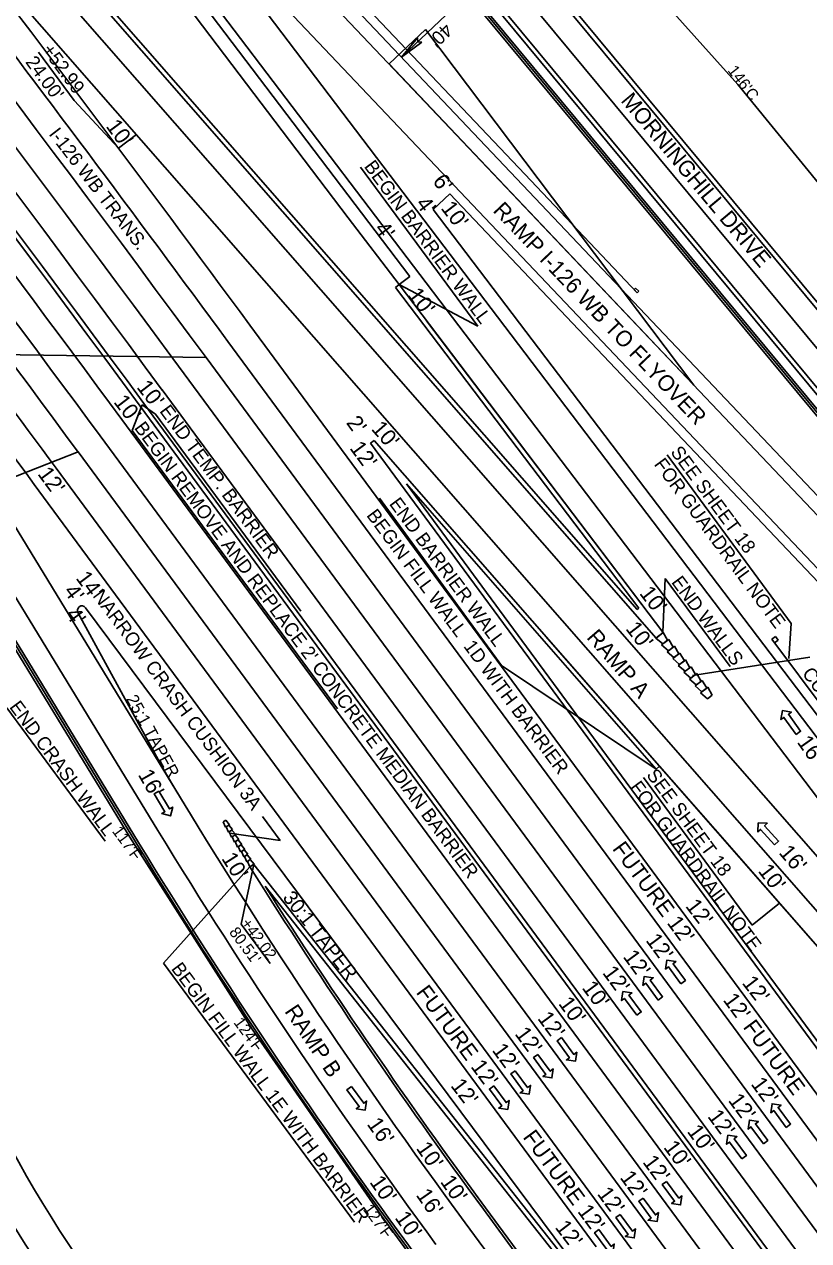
# Model space of a CAD drawing. Extents: x 1966090 to 1975830, y 788086 to 801233.
# Drawn here: x 1970435 to 1970780, y 796566 to 797102 of the extents above; entities that cross this region are included whole.
import ezdxf

# ---------------------------------------------------------------- set-up
doc = ezdxf.new("R2010")
doc.units = 0
for name, color, linetype in [('BR_PRESTRESSED BEAM', 7, 'Continuous'), ('BR_PROPOSED_DRAINAGE', 7, 'Continuous'), ('BR_REBAR', 7, 'Continuous'), ('RD_EX_Driveway_txCode', 7, 'Continuous'), ('RD_EX_RW_TX', 7, 'Continuous'), ('RD_EX_SU_Gas', 7, 'Continuous'), ('RD_EX_SU_H2O', 7, 'Continuous'), ('RD_EX_Survey_Limits', 7, 'Continuous'), ('RD_EX_TX_BldgApp_ELEV', 7, 'Continuous'), ('RD_EX_TX_Dam_ELEV', 7, 'Continuous'), ('RD_PD_Final_LnLine', 7, 'Continuous'), ('RD_PD_PaveShd', 7, 'Continuous'), ('RD_Sketch6', 7, 'Continuous'), ('RD_Sketch8', 7, 'Continuous'), ('RD_Sketch9', 7, 'Continuous')]:
    doc.layers.add(name, color=color, linetype=linetype)

msp = doc.modelspace()

# ---------------------------------------------------------------- linework, layer by layer
at = {"layer": 'BR_PRESTRESSED BEAM'}
for p, q in [((1970340.58, 797367.47), (1970655.12, 797035.82)), ((1970458.41, 797173.24), (1970577.36, 797016.6)), ((1970655.12, 797035.82), (1970704.66, 796983.58)), ((1970599.73, 796987.13), (1970577.36, 797016.6)), ((1970703.83, 796985.55), (1970703.29, 796985.03)), ((1970703.29, 796985.03), (1970704.66, 796983.58)), ((1970705.39, 796984.27), (1970703.83, 796985.55)), ((1970704.66, 796983.58), (1970705.39, 796984.27)), ((1970763.84, 796831), (1970765.45, 796832.2)), ((1970765.45, 796832.2), (1970766.64, 796830.6)), ((1970787.81, 796798.98), (1970763.84, 796831)), ((1970765.04, 796829.4), (1970763.84, 796831)), ((1970766.64, 796830.6), (1970765.04, 796829.4)), ((1970738.79, 796747.3), (1970714.42, 796775.13)), ((1970738.79, 796747.3), (1971033.24, 796411.1))]:
    msp.add_line(p, q, dxfattribs=at)
at = {"layer": 'BR_PROPOSED_DRAINAGE'}
for p, q in [((1970682.04, 797150.08), (1970748.85, 797075.26)), ((1970748.85, 797075.26), (1970875.59, 796920.37)), ((1970428.93, 796829.58), (1970481.23, 796743.9)), ((1970481.23, 796743.9), (1970535, 796659.31)), ((1970535, 796659.31), (1970591.97, 796577.07)), ((1970591.97, 796577.07), (1970651.22, 796496.51))]:
    msp.add_line(p, q, dxfattribs=at)
at = {"layer": 'BR_REBAR'}
for p, q in [((1970208.64, 797407.27), (1970712.9, 796831.5)), ((1970210.14, 797408.59), (1970704.59, 796844.03)), ((1970626.99, 797118.22), (1970963.53, 796712.5)), ((1970628.53, 797119.5), (1970965.07, 796713.78)), ((1970599.73, 796987.13), (1970598.14, 796985.92)), ((1970598.14, 796985.92), (1970705.39, 796844.7)), ((1970611.83, 796971.2), (1970715.91, 796834.14)), ((1970377.42, 796917.81), (1970485.02, 796741.53)), ((1970587.2, 796917.36), (1970588.81, 796918.54)), ((1970588.81, 796918.54), (1970714.42, 796775.13)), ((1970376.57, 796917.29), (1970484.16, 796741.01)), ((1970587.2, 796917.36), (1970691.5, 796775.88)), ((1970602.95, 796899.36), (1970693.11, 796777.07)), ((1970602.95, 796899.36), (1970712.91, 796773.81)), ((1970704.59, 796844.03), (1970705.39, 796844.7)), ((1970716, 796834.02), (1970712.94, 796831.45)), ((1970691.5, 796775.88), (1971027.63, 796319.93)), ((1970693.11, 796777.07), (1971029.24, 796321.12)), ((1970714.42, 796775.13), (1970712.91, 796773.81)), ((1970534.02, 796730.8), (1970535.71, 796731.87)), ((1970540.77, 796722.24), (1970711.09, 796506.63)), ((1970637.8, 796580.65), (1970763.63, 796409.96)), ((1970636.89, 796579.98), (1970762.72, 796409.3))]:
    msp.add_line(p, q, dxfattribs=at)
for radius, start in [(2527, 211.39766), (2526, 211.39766), (2490, 212.19585), (2488.88, 212.44528)]:
    msp.add_arc((1972641.14, 798057.51), radius, start, 216.39766, dxfattribs=at)
at = {"layer": 'RD_EX_Driveway_txCode'}
for points in [[(1970774.57, 796789.11), (1970776.52, 796790.5), (1970771.21, 796797.98), (1970772.53, 796798.92), (1970768.59, 796799.59), (1970767.92, 796795.64), (1970769.25, 796796.59)], [(1970493.96, 796764.12), (1970491.9, 796762.88), (1970496.64, 796755.03), (1970495.25, 796754.19), (1970499.13, 796753.23), (1970500.09, 796757.11), (1970498.7, 796756.27)], [(1970765.11, 796740.47), (1970766.88, 796742.09), (1970760.71, 796748.87), (1970761.91, 796749.97), (1970757.92, 796750.15), (1970757.73, 796746.16), (1970758.93, 796747.25)], [(1970723.89, 796679.33), (1970725.82, 796680.75), (1970720.38, 796688.13), (1970721.69, 796689.1), (1970717.73, 796689.7), (1970717.14, 796685.74), (1970718.45, 796686.71)], [(1970713.87, 796672.14), (1970715.8, 796673.56), (1970710.36, 796680.94), (1970711.67, 796681.91), (1970707.71, 796682.51), (1970707.11, 796678.55), (1970708.42, 796679.52)], [(1970704.45, 796665.47), (1970706.38, 796666.89), (1970700.94, 796674.27), (1970702.25, 796675.24), (1970698.3, 796675.84), (1970697.7, 796671.88), (1970699.01, 796672.85)], [(1970671.24, 796655.56), (1970669.31, 796654.14), (1970674.75, 796646.75), (1970673.44, 796645.79), (1970677.4, 796645.19), (1970677.99, 796649.15), (1970676.68, 796648.18)], [(1970660.9, 796648.18), (1970658.97, 796646.76), (1970664.41, 796639.38), (1970663.1, 796638.41), (1970667.05, 796637.81), (1970667.65, 796641.77), (1970666.34, 796640.8)], [(1970650.88, 796640.99), (1970648.94, 796639.57), (1970654.39, 796632.18), (1970653.07, 796631.22), (1970657.03, 796630.62), (1970657.63, 796634.57), (1970656.32, 796633.61)], [(1970578.74, 796634.06), (1970576.8, 796632.64), (1970582.22, 796625.24), (1970580.91, 796624.28), (1970584.86, 796623.67), (1970585.47, 796627.62), (1970584.16, 796626.66)], [(1970641.46, 796634.32), (1970639.53, 796632.9), (1970644.97, 796625.51), (1970643.66, 796624.55), (1970647.62, 796623.95), (1970648.21, 796627.91), (1970646.9, 796626.94)], [(1970770.19, 796616.07), (1970772.12, 796617.49), (1970766.67, 796624.87), (1970767.99, 796625.84), (1970764.03, 796626.44), (1970763.43, 796622.48), (1970764.74, 796623.45)], [(1970760.16, 796608.88), (1970762.1, 796610.3), (1970756.65, 796617.68), (1970757.96, 796618.65), (1970754.01, 796619.25), (1970753.41, 796615.29), (1970754.72, 796616.26)], [(1970750.75, 796602.21), (1970752.68, 796603.63), (1970747.24, 796611.01), (1970748.55, 796611.98), (1970744.59, 796612.58), (1970744, 796608.62), (1970745.31, 796609.59)], [(1970717.54, 796592.3), (1970715.61, 796590.88), (1970721.05, 796583.5), (1970719.74, 796582.53), (1970723.69, 796581.93), (1970724.29, 796585.89), (1970722.98, 796584.92)], [(1970707.19, 796584.92), (1970705.26, 796583.5), (1970710.7, 796576.12), (1970709.39, 796575.15), (1970713.35, 796574.55), (1970713.95, 796578.51), (1970712.64, 796577.54)], [(1970697.17, 796577.73), (1970695.24, 796576.31), (1970700.68, 796568.92), (1970699.37, 796567.96), (1970703.33, 796567.36), (1970703.92, 796571.32), (1970702.61, 796570.35)], [(1970687.76, 796571.06), (1970685.83, 796569.64), (1970691.27, 796562.26), (1970689.96, 796561.29), (1970693.91, 796560.69), (1970694.51, 796564.65), (1970693.2, 796563.68)]]:
    msp.add_lwpolyline(points, close=True, dxfattribs=at)
at = {"layer": 'RD_EX_SU_Gas'}
for p, q in [((1970514.75, 796954.97), (1971123.99, 796128.55)), ((1970505.09, 796947.85), (1971239.95, 795951.02)), ((1970468.06, 796920.55), (1971202.93, 795923.73)), ((1970458.41, 796913.43), (1971193.27, 795916.61))]:
    msp.add_line(p, q, dxfattribs=at)
for centre, radius, start, end in [((1958843.44, 788350.87), 14500, 36.397656, 39.566224), ((1958843.44, 788350.87), 14488, 36.397656, 39.566224), ((1961201.85, 790089.49), 11512, 36.397656, 39.351802), ((1961201.85, 790089.49), 11500, 36.397656, 39.351802), ((1970931.23, 796880.36), 600, 202.42407, 234.38356)]:
    msp.add_arc(centre, radius, start, end, dxfattribs=at)
at = {"layer": 'RD_EX_Survey_Limits'}
msp.add_line((1970371.42, 797456.09), (1970870.17, 796854.82), dxfattribs=at)
at = {"layer": 'RD_EX_TX_BldgApp_ELEV'}
for p, q in [((1970716.07, 796833.94), (1970712.87, 796831.53)), ((1970717.99, 796830.53), (1970716.07, 796833.94)), ((1970712.87, 796831.53), (1970715.86, 796828.92)), ((1970718.53, 796830.93), (1970715.33, 796828.52)), ((1970715.33, 796828.52), (1970718.32, 796825.91)), ((1970715.86, 796828.92), (1970717.99, 796830.53)), ((1970720.99, 796827.92), (1970717.79, 796825.51)), ((1970718.32, 796825.91), (1970720.45, 796827.51)), ((1970720.45, 796827.51), (1970718.53, 796830.93)), ((1970722.91, 796824.5), (1970720.99, 796827.92)), ((1970717.79, 796825.51), (1970720.78, 796822.9)), ((1970723.44, 796824.9), (1970720.25, 796822.5)), ((1970720.25, 796822.5), (1970723.24, 796819.88)), ((1970720.78, 796822.9), (1970722.91, 796824.5)), ((1970725.9, 796821.89), (1970722.71, 796819.48)), ((1970723.24, 796819.88), (1970725.37, 796821.49)), ((1970725.37, 796821.49), (1970723.44, 796824.9)), ((1970727.83, 796818.47), (1970725.9, 796821.89)), ((1970722.71, 796819.48), (1970725.7, 796816.87)), ((1970724.3, 796820.69), (1970724.3, 796820.69)), ((1970728.36, 796818.88), (1970725.17, 796816.47)), ((1970725.17, 796816.47), (1970728.16, 796813.86)), ((1970725.7, 796816.87), (1970727.83, 796818.47)), ((1970730.29, 796815.46), (1970728.36, 796818.88)), ((1970730.82, 796815.86), (1970727.62, 796813.45)), ((1970727.62, 796813.45), (1970730.62, 796810.84)), ((1970728.16, 796813.86), (1970730.29, 796815.46)), ((1970733.28, 796812.85), (1970730.08, 796810.44)), ((1970730.62, 796810.84), (1970732.75, 796812.45)), ((1970732.75, 796812.45), (1970730.82, 796815.86)), ((1970735.2, 796809.43), (1970733.28, 796812.85)), ((1970730.08, 796810.44), (1970733.07, 796807.83)), ((1970735.74, 796809.84), (1970732.54, 796807.43)), ((1970732.54, 796807.43), (1970735.53, 796804.82)), ((1970733.07, 796807.83), (1970735.2, 796809.43)), ((1970735.53, 796804.82), (1970737.66, 796806.42)), ((1970737.66, 796806.42), (1970735.74, 796809.84)), ((1970523.46, 796751.31), (1970522.22, 796750.55)), ((1970522.22, 796750.55), (1970523.25, 796748.18)), ((1970523.25, 796748.18), (1970525.12, 796749.33)), ((1970525.12, 796749.33), (1970523.46, 796751.31)), ((1970524.81, 796749.14), (1970523.57, 796748.37)), ((1970523.57, 796748.37), (1970524.6, 796746.01)), ((1970524.6, 796746.01), (1970526.46, 796747.16)), ((1970526.46, 796747.16), (1970524.81, 796749.14)), ((1970526.15, 796746.97), (1970524.91, 796746.2)), ((1970527.81, 796744.99), (1970526.15, 796746.97)), ((1970524.91, 796746.2), (1970525.95, 796743.84)), ((1970525.95, 796743.84), (1970527.81, 796744.99)), ((1970527.5, 796744.8), (1970526.26, 796744.03)), ((1970526.26, 796744.03), (1970527.29, 796741.66)), ((1970527.29, 796741.66), (1970529.15, 796742.82)), ((1970529.15, 796742.82), (1970527.5, 796744.8)), ((1970528.84, 796742.63), (1970527.6, 796741.86)), ((1970527.6, 796741.86), (1970528.64, 796739.49)), ((1970530.5, 796740.64), (1970528.84, 796742.63)), ((1970528.64, 796739.49), (1970530.5, 796740.64)), ((1970530.19, 796740.45), (1970528.95, 796739.68)), ((1970528.95, 796739.68), (1970529.98, 796737.32)), ((1970529.57, 796740.07), (1970529.57, 796740.07)), ((1970529.98, 796737.32), (1970531.85, 796738.47)), ((1970531.85, 796738.47), (1970530.19, 796740.45)), ((1970531.54, 796738.28), (1970530.29, 796737.51)), ((1970530.29, 796737.51), (1970531.33, 796735.15)), ((1970531.33, 796735.15), (1970533.19, 796736.3)), ((1970533.19, 796736.3), (1970531.54, 796738.28)), ((1970532.88, 796736.11), (1970531.64, 796735.34)), ((1970534.54, 796734.13), (1970532.88, 796736.11)), ((1970531.64, 796735.34), (1970532.68, 796732.97)), ((1970532.68, 796732.97), (1970534.54, 796734.13)), ((1970534.23, 796733.94), (1970532.99, 796733.17)), ((1970532.99, 796733.17), (1970534.02, 796730.8)), ((1970534.02, 796730.8), (1970535.88, 796731.96)), ((1970535.88, 796731.96), (1970534.23, 796733.94))]:
    msp.add_line(p, q, dxfattribs=at)
at = {"layer": 'RD_EX_TX_Dam_ELEV'}
msp.add_line((1970627.76, 797118.86), (1970899.28, 796791.53), dxfattribs=at)
at = {"layer": 'RD_PD_Final_LnLine'}
for p, q in [((1970611.34, 797099.41), (1970595.38, 797084.28)), ((1970611.34, 797099.41), (1970729.57, 796942.79)), ((1970595.38, 797084.28), (1970729.57, 796942.79))]:
    msp.add_line(p, q, dxfattribs=at)
at = {"layer": 'RD_PD_PaveShd'}
for p, q in [((1970381.42, 797464.39), (1970880.17, 796863.12)), ((1970361.41, 797447.79), (1970860.16, 796846.52)), ((1970208.64, 797407.27), (1970712.9, 796831.5)), ((1970337.68, 797364.72), (1970967.22, 796700.93)), ((1970463.19, 797176.87), (1970604.51, 796990.76)), ((1970476.15, 797047.23), (1970484.16, 797053.22)), ((1970622.06, 797027.08), (1970614.81, 797020.2)), ((1970622.06, 797027.08), (1970948.35, 796683.04)), ((1970614.81, 797020.2), (1971000.85, 796511.82)), ((1970604.51, 796990.76), (1970599.73, 796987.13)), ((1970599.73, 796987.13), (1970715.91, 796834.14)), ((1970487.38, 796934.79), (1971048.19, 796174.06)), ((1970485.77, 796933.61), (1971046.58, 796172.88)), ((1970377.42, 796917.81), (1970485.02, 796741.53)), ((1970587.2, 796917.36), (1970588.81, 796918.54)), ((1970714.42, 796775.13), (1970588.81, 796918.54)), ((1970587.2, 796917.36), (1970691.5, 796775.88)), ((1970664.28, 796832.37), (1971096.42, 796338.96)), ((1970691.5, 796775.88), (1971027.63, 796319.93)), ((1970534.02, 796730.8), (1970535.72, 796731.87)), ((1970535.72, 796731.87), (1970712.68, 796507.84)), ((1970636.89, 796579.98), (1970762.72, 796409.3))]:
    msp.add_line(p, q, dxfattribs=at)
for centre, radius, start, end in [((1972641.14, 798057.51), 2526, 211.39766, 216.39766), ((1972641.14, 798057.51), 2490, 212.19585, 216.39766), ((1970931.23, 796880.36), 572, 203.6552, 226.0941), ((1970931.23, 796880.36), 624, 203.63926, 233.79058)]:
    msp.add_arc(centre, radius, start, end, dxfattribs=at)
at = {"layer": 'RD_Sketch6'}
for p, q in [((1970600.87, 797087.33), (1970629.83, 797114.8)), ((1970607.8, 797095.84), (1970600.87, 797087.33)), ((1970607.99, 797094.09), (1970607.8, 797095.84)), ((1970600.87, 797087.33), (1970609.73, 797093.81)), ((1970609.73, 797093.81), (1970607.99, 797094.09)), ((1970582.83, 797038.79), (1970634.41, 796968.83)), ((1970634.41, 796968.83), (1970599.73, 796987.13)), ((1970296.39, 796958.41), (1970514.75, 796954.97)), ((1970482.24, 796922.91), (1970486.58, 796934.2)), ((1970492.48, 796930.11), (1970486.58, 796934.2)), ((1970556.43, 796843.37), (1970492.48, 796930.11)), ((1970482.24, 796922.91), (1970572.57, 796800.38)), ((1970334.19, 796864.86), (1970458.41, 796913.43)), ((1970717.76, 796912.12), (1970772.42, 796837.96)), ((1970591.09, 796893.11), (1970644.85, 796819.4)), ((1970716.9, 796857.74), (1970715.91, 796834.15)), ((1970716.9, 796857.74), (1970745.5, 796818.94)), ((1970772.42, 796837.96), (1970771.39, 796822.52)), ((1970780.63, 796823.08), (1970728.99, 796815.02)), ((1970644.85, 796819.4), (1970712.91, 796773.81)), ((1970470.37, 796742.03), (1970427.09, 796800.73)), ((1970707.36, 796770.04), (1970755.29, 796705.02)), ((1970539.64, 796752.88), (1970547.36, 796742.4)), ((1970547.36, 796742.4), (1970525.17, 796745.61)), ((1970496.06, 796688.41), (1970534.02, 796730.8)), ((1970767.34, 796714.71), (1970755.29, 796705.02)), ((1970580.15, 796574.35), (1970496.06, 796688.41))]:
    msp.add_line(p, q, dxfattribs=at)
for points in [[(1970441.01, 797089.53), (1970456.74, 797068.19), (1970476.15, 797047.23)], [(1970542.97, 796688.21), (1970530.21, 796705.51), (1970535.72, 796731.87)]]:
    msp.add_lwpolyline(points, dxfattribs=at)
at = {"layer": 'RD_Sketch8'}
for p, q in [((1970018.76, 797608.9), (1970931.78, 796566.41)), ((1970379.89, 797463.11), (1970878.63, 796861.84)), ((1970362.95, 797449.06), (1970861.7, 796847.8)), ((1970333.32, 797360.59), (1970962.87, 796696.8)), ((1970331.93, 797227.03), (1971103.94, 796345.55)), ((1970466.37, 797179.29), (1970931.78, 796566.41)), ((1970499.5, 797162.12), (1970951.26, 796685.79)), ((1970499.5, 797162.12), (1971082.9, 796393.86)), ((1970534.07, 796969.21), (1971268.93, 795972.38)), ((1970524.41, 796962.09), (1971259.27, 795965.26)), ((1970495.43, 796940.73), (1971230.29, 795943.9)), ((1970399.62, 796931.35), (1970507.21, 796755.07)), ((1970385.96, 796923.02), (1970493.55, 796746.74)), ((1970477.72, 796927.67), (1971212.58, 795930.85)), ((1970448.75, 796906.31), (1970838.13, 796378.12)), ((1970439.11, 796899.16), (1970686.58, 796563.47)), ((1970461.73, 796844.88), (1970712.68, 796507.84)), ((1970458.51, 796842.51), (1970496.26, 796773.18)), ((1970628.84, 796574.04), (1970754.67, 796403.36))]:
    msp.add_line(p, q, dxfattribs=at)
for centre, radius, start, end in [((1958843.44, 788350.87), 14476, 36.397656, 39.566224), ((1961201.85, 790089.49), 11524, 36.397656, 39.351802), ((1961201.85, 790089.49), 11488, 36.397656, 38.049017), ((1958843.44, 788350.87), 14524, 36.397656, 37.323179), ((1958843.44, 788350.87), 14512, 36.397656, 37.215454), ((1958787.09, 788309.34), 14476, 36.397503, 37.164449), ((1970460.12, 796843.69), 2, 36.3977, 216.3977), ((1972641.14, 798057.51), 2500, 210.91274, 216.39766), ((1972641.14, 798057.51), 2516, 211.39766, 216.39766), ((1970931.23, 796880.36), 588, 203.63926, 234.98689), ((1970931.23, 796880.36), 612, 203.63926, 234.98689)]:
    msp.add_arc(centre, radius, start, end, dxfattribs=at)
at = {"layer": 'RD_Sketch9'}
for p, q in [((1970487.38, 796934.79), (1971048.19, 796174.06)), ((1970485.77, 796933.61), (1971046.58, 796172.88))]:
    msp.add_line(p, q, dxfattribs=at)
for centre, radius, end in [((1958787.09, 788309.34), 14534, 39.713887), ((1958843.44, 788350.87), 14466, 39.566224)]:
    msp.add_arc(centre, radius, 36.397656, end, dxfattribs=at)

# ---------------------------------------------------------------- texts
at = {"layer": 'RD_EX_Driveway_txCode'}
for s, height, rotation, p in [("10'", 7, 306.3992, (1970470.37, 797056.82)), ("6'", 7, 307.212, (1970614.23, 797032.57)), ("4'", 7, 307.212, (1970606.79, 797022.66)), ("10'", 7, 307.212, (1970617.9, 797020.74)), ("4'", 7, 307.212, (1970588.63, 797011.67)), ("10'", 7, 307.212, (1970603.2, 796982.56)), ("10'", 7, 307.533, (1970483.92, 796941.89)), ("10'", 7, 307.533, (1970473.75, 796935.41)), ("2'", 7, 306.3977, (1970576.21, 796926.24)), ("10'", 7, 311.212, (1970587.16, 796923.45)), ("12'", 7, 306.3977, (1970577.73, 796915.1)), ("12'", 7, 306.3975, (1970440.3, 796903.76)), ("14'", 7, 306.6704, (1970457.13, 796857.86)), ("4'", 7, 306.6704, (1970451.81, 796852.07)), ("10'", 7, 307.5314, (1970705.3, 796851.16)), ("4'", 7, 306.6704, (1970452.58, 796841.82)), ("10'", 7, 307.5314, (1970699.23, 796835.56)), ("16'", 7, 305.3319, (1970774.75, 796785.64)), ("16'", 7, 299.71, (1970484.61, 796771.37)), ("FUTURE 12'", 7, 306.3976, (1970693.4, 796738.69)), ("10'", 7, 302.4184, (1970521.31, 796734.5)), ("16'", 7, 310.5549, (1970766.66, 796736.86)), ("10'", 7, 307.5314, (1970757.56, 796728.85)), ('30:1 TAPER', 6.3, 307.9977, (1970548.21, 796717.11)), ("12'", 7, 307.5314, (1970725.56, 796713.42)), ("12'", 7, 306.3976, (1970708.11, 796698.37)), ("12'", 7, 306.3976, (1970698.09, 796691.17)), ("12'", 7, 306.3976, (1970689.02, 796684.1)), ("12'", 7, 307.5314, (1970750.5, 796679.59)), ("FUTURE 12'", 7, 306.3976, (1970606.97, 796675.44)), ("10'", 7, 306.3992, (1970680.01, 796677.48)), ("10'", 7, 306.3992, (1970669.65, 796670.51)), ("12' FUTURE", 7, 306.3976, (1970742.15, 796672.1)), ("12'", 7, 306.3976, (1970660.43, 796664.01)), ("12'", 7, 306.3976, (1970650.44, 796657.2)), ("12'", 7, 306.3976, (1970640.42, 796650)), ("12'", 7, 307.533, (1970622.16, 796634.37)), ("12'", 7, 306.3976, (1970754.41, 796635.11)), ("12'", 7, 306.3976, (1970744.39, 796627.91)), ("12'", 7, 306.3976, (1970735.32, 796620.84)), ("16'", 7, 304.8362, (1970585.36, 796617.48)), ("FUTURE 12'", 7, 306.3976, (1970653.98, 796611.69)), ("10'", 7, 306.3992, (1970726.3, 796614.22)), ("10'", 7, 304.8362, (1970607, 796606.85)), ("10'", 7, 306.3992, (1970715.94, 796607.25)), ("12'", 7, 306.3976, (1970706.73, 796600.75)), ("12'", 7, 306.3976, (1970696.74, 796593.94)), ("10'", 7, 304.8362, (1970586.51, 796591.96)), ("10'", 7, 304.8362, (1970617.62, 796592.13)), ("16'", 7, 304.8362, (1970606.97, 796586.23)), ("12'", 7, 306.3976, (1970686.72, 796586.75)), ("10'", 7, 304.8362, (1970597.63, 796576.24)), ("12'", 7, 307.533, (1970668.15, 796571.98))]:
    msp.add_text(s, height=height, rotation=rotation, dxfattribs=at).set_placement(p)
at = {"layer": 'RD_EX_RW_TX'}
for s, rotation, p in [("146'C", 307.212, (1970744.22, 797081.36)), ("117'F", 306.3977, (1970473.16, 796746.42)), ("124'F", 306.3977, (1970526.65, 796662.21)), ("127'F", 306.3977, (1970583.62, 796579.97))]:
    msp.add_text(s, height=5, rotation=rotation, dxfattribs=at).set_placement(p)
at = {"layer": 'RD_EX_SU_H2O'}
for s, rotation, p in [('MORNINGHILL DRIVE', 309.8296, (1970697.12, 797068)), ('RAMP I-126 WB TO FLYOVER', 313.5092, (1970640.77, 797019.47)), ('RAMP A', 310.7291, (1970682.03, 796831.62)), ('RAMP B', 303.9445, (1970549.1, 796667.14))]:
    msp.add_text(s, height=7, rotation=rotation, dxfattribs=at).set_placement(p)
at = {"layer": 'RD_Sketch6'}
for s, height, rotation, p in [("40'", 6, 223.4833, (1970619.88, 797102.68)), ('+52.99', 6, 306.3977, (1970442.22, 797090.42)), ("24.00'", 6, 306.3977, (1970434.97, 797085.08)), ('I-126 WB TRANS.', 5.9996, 307.588, (1970445.23, 797053.35)), ('BEGIN BARRIER WALL', 5.9996, 306.5574, (1970584.09, 797039.1)), ('END TEMP. BARRIER', 5.9996, 306.5575, (1970494.01, 796931.41)), ("BEGIN REMOVE AND REPLACE 2' CONCRETE MEDIAN BARRIER ", 5.9996, 306.5575, (1970482.89, 796924.01)), ('SEE SHEET 18', 5.9996, 306.4867, (1970719.01, 796913.34)), ('FOR GUARDRAIL NOTE', 5.9996, 306.4867, (1970711.77, 796907.98)), ('END BARRIER WALL', 5.9996, 306.5574, (1970595.15, 796890.58)), ('BEGIN FILL WALL  1D WITH BARRIER', 5.9996, 306.5574, (1970585.14, 796885.51)), ('END WALLS', 6, 306.5574, (1970719.4, 796856.07)), ('NARROW CRASH CUSHION 3A', 5.9996, 306.5574, (1970464.58, 796850.05)), ('CUSHION 3A', 6, 306.5574, (1970776.95, 796815.91)), ('25:1 TAPER', 5.4, 298.5692, (1970479.37, 796804.74)), ('END CRASH WALL', 5.9996, 306.5574, (1970427.89, 796801.11)), ('SEE SHEET 18', 5.9996, 306.4867, (1970708.39, 796771.17)), ('FOR GUARDRAIL NOTE', 5.9996, 306.4867, (1970701.15, 796765.82)), ("80.51'", 5, 306.3977, (1970524.67, 796701.98)), ('+42.02', 5, 306.3977, (1970529.95, 796705.87)), ('BEGIN FILL WALL 1E WITH BARRIER', 5.9996, 306.5574, (1970499.16, 796685.89))]:
    msp.add_text(s, height=height, rotation=rotation, dxfattribs=at).set_placement(p)

doc.saveas('drawing.dxf')
